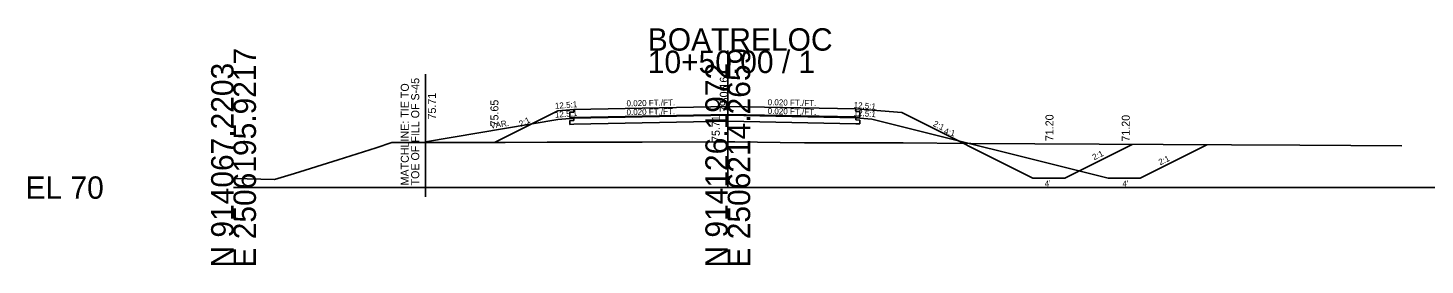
# Model space of a CAD drawing. Extents: x -26 to 403, y -10 to 2549.
# Drawn here: x -25.7 to 148.9, y -9.7 to 20 of the extents above; entities that cross this region are included whole.
import ezdxf

# ---------------------------------------------------------------- set-up
doc = ezdxf.new("R2010")
doc.units = 0
for name, color, linetype in [('RD_GPK_XS_Cell', 7, 'Continuous'), ('RD_Sketch9', 7, 'Continuous'), ('RD_XS_EarthShd', 7, 'Continuous'), ('RD_XS_ExGround', 7, 'Continuous'), ('RD_XS_Pave', 7, 'Continuous'), ('RD_XS_PaveOvlay', 7, 'Continuous'), ('RD_XS_TieSlope', 7, 'Continuous'), ('RD_XS_TX_Elev_EX', 7, 'Continuous'), ('RD_XS_TX_Elev_PR', 7, 'Continuous'), ('RD_XS_TX_ShdSlope', 7, 'Continuous'), ('RD_XS_TX_Slope', 7, 'Continuous')]:
    doc.layers.add(name, color=color, linetype=linetype)

msp = doc.modelspace()

# ---------------------------------------------------------------- linework, layer by layer
at = {"layer": 'RD_GPK_XS_Cell'}
for p, q in [((61.76, 0), (61.76, 17.13)), ((0, 0), (61.76, 0)), ((61.76, 0), (261.76, 0))]:
    msp.add_line(p, q, dxfattribs=at)
at = {"layer": 'RD_Sketch9'}
for p, q in [((40.53, 9.61), (32.6, 5.65)), ((42.53, 9.77), (40.53, 9.61)), ((42.03, 9.43), (42.53, 9.44)), ((42.03, 8.76), (42.03, 9.43)), ((42.53, 8.77), (42.03, 8.76)), ((61.76, 10.16), (42.53, 9.77)), ((42.53, 9.44), (42.53, 9.77)), ((42.53, 8.77), (61.76, 9.16)), ((77.76, 9.84), (61.76, 10.16)), ((61.76, 9.16), (77.76, 8.84)), ((77.76, 9.51), (77.76, 9.84)), ((77.76, 9.84), (83.5, 9.38)), ((78.26, 9.5), (77.76, 9.51)), ((77.76, 8.84), (78.26, 8.83)), ((78.26, 8.83), (78.26, 9.5)), ((83.5, 9.38), (99.86, 1.2)), ((112.29, 5.41), (103.86, 1.2)), ((99.86, 1.2), (103.86, 1.2))]:
    msp.add_line(p, q, dxfattribs=at)
at = {"layer": 'RD_XS_EarthShd'}
for p, q in [((77.76, 8.74), (79.76, 8.58)), ((42.53, 8.68), (40.53, 8.52))]:
    msp.add_line(p, q, dxfattribs=at)
at = {"layer": 'RD_XS_ExGround'}
for p, q in [((17.82, 4.97), (19.77, 5.63)), ((19.77, 5.63), (33.01, 5.65)), ((33.01, 5.65), (33.93, 5.65)), ((33.93, 5.65), (39.17, 5.67)), ((39.17, 5.67), (51.05, 5.69)), ((51.05, 5.69), (61.76, 5.71)), ((61.76, 5.71), (62.65, 5.71)), ((62.65, 5.71), (68.3, 5.65)), ((68.3, 5.65), (71.34, 5.61)), ((71.34, 5.61), (72.79, 5.61)), ((72.79, 5.61), (83.69, 5.58)), ((83.69, 5.58), (92.15, 5.53)), ((92.15, 5.53), (116.17, 5.39)), ((116.17, 5.39), (133.24, 5.29)), ((133.24, 5.29), (145.99, 5.21)), ((7.62, 1.76), (13.06, 3.49)), ((13.06, 3.49), (17.82, 4.97)), ((5.1, 1.02), (7.62, 1.76)), ((0, 1.15), (5.1, 1.02))]:
    msp.add_line(p, q, dxfattribs=at)
at = {"layer": 'RD_XS_Pave'}
for p, q in [((77.76, 8.46), (77.76, 8.74)), ((42.03, 8.39), (42.53, 8.4)), ((42.03, 7.91), (42.03, 8.39)), ((42.53, 7.92), (42.03, 7.91)), ((42.53, 8.4), (42.53, 8.68)), ((42.53, 7.92), (61.76, 8.3)), ((61.76, 8.3), (77.76, 7.98)), ((78.26, 8.45), (77.76, 8.46)), ((77.76, 7.98), (78.26, 7.97)), ((78.26, 7.97), (78.26, 8.45))]:
    msp.add_line(p, q, dxfattribs=at)
at = {"layer": 'RD_XS_PaveOvlay'}
for p, q in [((61.76, 9.06), (42.53, 8.68)), ((77.76, 8.74), (61.76, 9.06))]:
    msp.add_line(p, q, dxfattribs=at)
at = {"layer": 'RD_XS_TieSlope'}
for p, q in [((23.98, -1.17), (23.98, 14.21)), ((40.53, 8.52), (23.98, 5.71)), ((79.76, 8.58), (109.29, 1.2)), ((121.61, 5.36), (113.29, 1.2)), ((109.29, 1.2), (113.29, 1.2))]:
    msp.add_line(p, q, dxfattribs=at)

# ---------------------------------------------------------------- texts
at = {"layer": 'RD_GPK_XS_Cell'}
for s, p in [('BOATRELOC', (51.76, 17.13)), ('10+50.00 / 1', (51.76, 14.33)), ('EL 70', (-26, -1.4))]:
    msp.add_text(s, height=2.8, dxfattribs=at).set_placement(p)
for s, p in [('E 2506195.9217', (2.8, -10)), ('E 2506214.2659', (64.56, -10)), ('N 914067.2203', (0, -10)), ('N 914126.1972', (61.76, -10))]:
    msp.add_text(s, height=2.8, rotation=90, dxfattribs=at).set_placement(p)
at = {"layer": 'RD_Sketch9'}
for s, height, rotation, p in [(' 80.16', 1, 90, (61.76, 10.16)), (' 80.16', 1, 90, (61.76, 10.16)), ('75.65', 1, 90, (33.1, 7.65)), ('12.5:1', 0.75, 4.5739, (40.19, 9.84)), ('0.020 FT./FT.', 0.75, 1.1458, (49.11, 10.16)), ('0.020 FT./FT.', 0.75, 358.8542, (66.74, 10.31)), ('12.5:1', 0.75, 355.4261, (77.46, 9.98)), ('2:1', 0.75, 26.5651, (35.9, 7.58)), ('71.20', 1, 90, (102.46, 5.81)), ('2:1', 0.75, 333.4349, (87.34, 7.74)), ('2:1', 0.75, 25.4593, (107.53, 3.41)), ("4'", 0.75, 2.665, (101.38, 0.12))]:
    msp.add_text(s, height=height, rotation=rotation, dxfattribs=at).set_placement(p)
at = {"layer": 'RD_XS_TX_Elev_EX'}
msp.add_text('75.71', height=1, rotation=90, dxfattribs=at).set_placement((60.76, 5.71))
at = {"layer": 'RD_XS_TX_Elev_PR'}
for s, p in [('MATCHLINE: TIE TO', (21.9, 0.27)), ('TOE OF FILL OF S-45', (23.2, 0.27)), (' 79.06', (61.76, 9.06)), ('75.71', (25.29, 8.52)), ('71.20', (111.99, 5.75))]:
    msp.add_text(s, height=1, rotation=90, dxfattribs=at).set_placement(p)
at = {"layer": 'RD_XS_TX_ShdSlope'}
for rotation, p in [(4.5739, (40.19, 8.74)), (355.4261, (77.46, 9.02))]:
    msp.add_text('12.5:1', height=0.75, rotation=rotation, dxfattribs=at).set_placement(p)
at = {"layer": 'RD_XS_TX_Slope'}
for s, rotation, p in [('0.020 FT./FT.', 1.1458, (49.11, 9.06)), ('0.020 FT./FT.', 358.8542, (66.74, 9.21)), ('VAR.', 9.6397, (32.15, 7.35)), ('4:1', 344.3384, (88.71, 6.76)), ('2:1', 25.4593, (115.8, 2.79)), ("4'", 2.665, (111.1, 0.12))]:
    msp.add_text(s, height=0.75, rotation=rotation, dxfattribs=at).set_placement(p)

doc.saveas('drawing.dxf')
